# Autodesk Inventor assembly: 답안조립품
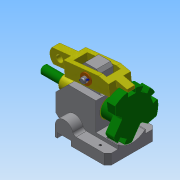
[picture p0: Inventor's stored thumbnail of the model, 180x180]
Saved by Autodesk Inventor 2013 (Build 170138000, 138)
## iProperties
Created: 2016-11
Part Number: 답안조립품
Document SubType Name: Assembly
Designer: Administrator
Author: Administrator
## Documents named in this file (8)
- C:\Users\Administrator\Desktop\461108V1035\답안조립품.iam
- C:\Users\Administrator\Desktop\461108V1035\본체.ipt
- C:\Users\Administrator\Desktop\461108V1035\부시.ipt
- C:\Users\Administrator\Desktop\461108V1035\분할대.ipt
- C:\Users\Administrator\Desktop\461108V1035\분할축.ipt
- C:\Users\Administrator\Desktop\461108V1035\와셔.ipt
- C:\Users\Administrator\Desktop\461108V1035\원통형핀.ipt
- C:\Users\Administrator\Desktop\461108V1035\클레비스핀.ipt
